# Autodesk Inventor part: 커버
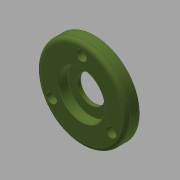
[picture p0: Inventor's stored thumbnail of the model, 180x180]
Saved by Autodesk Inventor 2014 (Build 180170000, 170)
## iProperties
Created: 2016-06
Part Number: 커버
Material: 알루미늄 6061
Document SubType Name: Modeling
Designer: mduedu
Density: 2.71 g/cm^3
Appearance: 올리브 녹색
Author: mduedu
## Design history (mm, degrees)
sketch "스케치1"
  geometry: C1 r 34 at (0, 0); 1 further point
  constraints: 1 centre point, 1 coincident
  dimensions: "d0" = 68 diameter of C1
extrude "돌출1" new body sketch "스케치1" distance "d2" = 10; taper "d3" = 0 deg
sketch "스케치2"
  geometry: C1 r 21 at (0, 0); 1 further point
  constraints: 1 centre point, 1 coincident
  dimensions: "d4" = 42 diameter of C1
extrude "돌출2" join sketch "스케치2" distance "d6" = 3; taper "d7" = 0 deg
fillet "모깎기1" dims "d8" = 3
hole "구멍1" diameter "d11" = 35; stored, may be unused: countersink angle "d15" = 90 deg, drill point angle "d17" = 0 deg; dims "d9" = 10, "d10" = 10, "d12" = 6, "d13" = 4, "d14" = 2, "d16" = 3
hole "구멍2" diameter "d20" = 35; stored, may be unused: countersink angle "d24" = 90 deg, drill point angle "d26" = 0 deg; dims "d21" = 6, "d22" = 4, "d23" = 2, "d25" = 7.3, "d73" = 10, "d74" = 10
hole "구멍3" diameter "d29" = 21; stored, may be unused: countersink angle "d33" = 90 deg, drill point angle "d35" = 0 deg; dims "d27" = 10, "d28" = 10, "d30" = 6, "d31" = 4, "d32" = 2, "d34" = 5
fillet "모깎기2" dims "d36" = 3
fillet "모깎기3" dims "d37" = 0.1
chamfer "모따기1" distance "d38" = 0.7; stored, may be unused: second distance "d39" = 2, angle "d40" = 30 deg
chamfer "모따기2" distance "d42" = 0.5; stored, may be unused: second distance "d43" = 2, angle "d44" = 30 deg
sketch "스케치5" dims "d60" = 52
  geometry: 3 further points
  constraints: 2 vertical alignment, 1 coincident, 2 other
hole "구멍5" sketch "스케치5" at (0, 26) diameter "d61" = 4.5; stored, may be unused: countersink angle "d65" = 90 deg, drill point angle "d67" = 118 deg; dims "d62" = 6, "d63" = 8, "d64" = 4.6, "d66" = 8
node "솔리드1"
pattern_circular "원형 패턴1" dims angle "d69" = 360 deg
